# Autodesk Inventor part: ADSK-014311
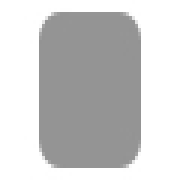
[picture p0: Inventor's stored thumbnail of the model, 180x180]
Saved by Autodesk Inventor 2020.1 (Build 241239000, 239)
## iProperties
Created: 2019-01
Part Number: ADSK-014311
Material: Stahl, weich
Document SubType Name: Modeling
Designer: lutzd
Language: de-DE
Size Designation: 5 x 39,384472 x 39,384472
Categories: <MemberInstance><Categories><Category DisplayName="Sonstige Bauteile" InternalName="5aa15e00-363f-49f2-933f-16f664388e3f" Mnemonic="OTHER"><Category DisplayName
Mass: 60.0398 g
Surface Area: 38.0412 cm^2
Volume: 7.64838 cm^3
Density: 7.85 g/cm^3
Appearance: Semi-Polished(8)
IsCustomPart: 1
Title: end cap
Author: lutzd
Revision Number: -
DocNumber: ADSK-014311
Folder: 01 - Themengebiete\Simplification\01 - Packaging machine\
VDS_Category: 3D Komponenten
VDS_NumSchm: Autodesk
Dimensions: 39,4x39,4x5 mm
Mass: 0,06 kg
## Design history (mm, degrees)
sketch "Sketch1"
  geometry: L1 (0, 20.175)-(0, -21.446); L2 (-20.203, 0)-(20.169, 0); L3 (-19.692, 19.692)-(19.692, 19.692); L4 (19.692, 19.692)-(19.692, -19.692); L5 (19.692, -19.692)-(-19.692, -19.692); L6 (-19.692, -19.692)-(-19.692, 19.692); 1 further point
  constraints: 12 end point, 2 horizontal, 2 parallel, 2 point on line, 1 perpendicular, 1 vertical
  dimensions: "d0" = 39.38447 distance between parallel lines of L5 L3 (= height); "d1" = 19.69224 distance between parallel lines of L2 L3 (= 0.5 x height); "d2" = 39.38447 distance between parallel lines of L6 L4 (= width); "d3" = 19.69224 distance between parallel lines of L6 L1 (= 0.5 x width)
extrude "Extrusion1" new body sketch "Sketch1" distance "d4" = 5 (= thickness); taper "d5" = 0 deg
fillet "Fillet1" dims "d6" = 5 (= fillet), "d7" = 0, "fillet" = 5 [user parameter; used in 1 equation term]
chamfer "Chamfer1" distance "d8" = 0 (computed from chamfer); stored, may be unused: second distance "d9" = 2, angle "d10" = 45 deg; dims "d11" = 0, "chamfer" = 0 [user parameter; used in 1 equation term]
body "Solid1"
other parameters: "thickness" = 5 [user parameter; used in 1 equation term], "width" = 39.38447 [user parameter; used in 2 equation terms], "height" = 39.38447 [user parameter; used in 2 equation terms]
